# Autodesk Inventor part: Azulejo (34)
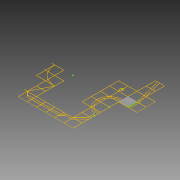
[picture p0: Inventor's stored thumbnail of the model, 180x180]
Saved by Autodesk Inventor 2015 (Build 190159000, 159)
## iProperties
Created: 2015-04
Part Number: Azulejo (34)
Material: Genérico
Document SubType Name: Modeling
Designer: Felipe
Density: 1 g/cm^3
Appearance: Padrão
Author: Felipe
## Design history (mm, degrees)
sketch "Sketch1"
  geometry: L1 (-1510, -7490)-(-1510, -6010); L2 (-3010, -1490)-(-3010, -10); L3 (-2990, 10)-(-1510, 10); L4 (-1510, -10)-(-2990, -10); L5 (-1510, -1490)-(-1510, -10); L6 (-1490, -10)-(-1490, -1490); L7 (-1490, -1490)-(-10, -1490); L8 (-10, -1510)-(-1490, -1510); L9 (-10, -2990)-(-10, -1510); L10 (-10, -5990)-(-10, -4510); L11 (-1490, -7490)-(-10, -7490); L12 (4490, -6010)-(3010, -6010); L13 (10, -1510)-(10, -2990); L14 (10, -3010)-(10, -4490); L15 (10, -4510)-(10, -5990); L16 (10, -5990)-(1490, -5990); L17 (1490, -6010)-(10, -6010); L18 (10, -7490)-(1490, -7490); L19 (1510, -5990)-(2990, -5990); L20 (2990, -6010)-(1510, -6010); L21 (1510, -7490)-(2990, -7490); L22 (4490, 1510)-(4490, 2990); L23 (4490, 10)-(4490, 1490); L24 (4490, -1490)-(4490, -10); L25 (4490, -2990)-(4490, -1510); L26 (3010, -5990)-(4490, -5990); L27 (3010, -7490)-(4490, -7490); L28 (4510, 3010)-(5990, 3010); L29 (5990, 2990)-(4510, 2990); L30 (4510, 2990)-(4510, 1510); L31 (4510, 1510)-(5990, 1510); L32 (5990, 1510)-(5990, 1740.185); L33 (5990, 1760.2)-(5990, 2259.8); L34 (5990, 2279.815)-(5990, 2990); L35 (5990, 1490)-(4510, 1490); L36 (4510, 1490)-(4510, 10); L37 (4510, 10)-(5990, 10); L38 (5990, 10)-(5990, 1490); L39 (5975.983, -10)-(4510, -10); L40 (4510, -10)-(4510, -1490); L41 (5990, -1510)-(5782.897, -1510); L42 (5782.897, -1510)-(5688.66, -1510); L43 (5668.66, -1510)-(5482.895, -1510); L44 (5482.895, -1510)-(5388.656, -1510); L45 (5368.656, -1510)-(4510, -1510); L46 (4510, -1510)-(4510, -2990); L47 (4510, -2990)-(5975.983, -2990); L48 (5990, -2975.728)-(5990, -2837.377); L49 (5990, -2837.377)-(5990, -2536.247); L50 (5990, -2500.476)-(5990, -2317.632); L51 (5990, -2317.632)-(5990, -1510); L52 (5990, -3010)-(4510, -3010); L53 (5990, -4490)-(5990, -3010); L54 (4510, -5990)-(5990, -5990); L55 (5990, -5990)-(5990, -4510); L56 (4510, -7490)-(5990, -7490); L57 (5990, -7490)-(5990, -6310); L58 (5990, -6290)-(5990, -6010); L59 (7490, 4510)-(7490, 5990); L60 (6010, 3010)-(7490, 3010); L61 (7490, 3010)-(7490, 4490); L62 (7490, 2990)-(6010, 2990); L63 (6010, 2990)-(6010, 2279.815); L64 (6010, 2259.8)-(6010, 1760.2)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; A1 r 250 centre (6000, 2010) between (5990, 2259.8) and (5990, 1760.2); A2 r 250 centre (6000, 2010) between (6010, 1760.2) and (6010, 2259.8); A3 r 270 centre (6000, 2010) between (5990, 2279.815) and (5990, 1740.185); A4 r 270 centre (6000, 2010) between (6010, 1740.185) and (6010, 2279.815); A5 r 3010.017 centre (0, 0) between (-1490, -2615.358) and (-346.554, -2990); A6 r 2990.017 centre (0, 0) between (-1490, -2592.316) and (-10, -2990); A7 r 3010.017 centre (0, 0) between (-2603.863, -1510) and (-1510, -2603.863); A8 r 2990.017 centre (0, 0) between (-2580.717, -1510) and (-1510, -2580.717); A9 r 3010.017 centre (0, 0) between (-2990, -346.554) and (-2615.358, -1490); A10 r 2990.017 centre (0, 0) between (-2990, -10) and (-2592.316, -1490); A11 r 2131.367 centre (7500, -1500) between (7490, 631.344) and (6010, 24.017); A12 r 2131.367 centre (7500, -1500) between (5975.983, -10) and (5368.656, -1490); A13 r 2131.367 centre (7500, -1500) between (5368.656, -1510) and (5975.983, -2990); A14 r 2131.367 centre (7500, -1500) between (6010, -3024.017) and (7190, -3608.703); A15 r 1831.367 centre (7500, -1500) between (7490.321, 331.342) and (6463.753, 10); A16 r 1831.367 centre (7500, -1500) between (6435.196, -10) and (6010, -435.196); A17 r 1831.367 centre (7500, -1500) between (5990, -463.753) and (5668.66, -1490); A18 r 1831.367 centre (7500, -1500) between (5668.66, -1510) and (5990, -2536.247); A19 r 1831.367 centre (7500, -1500) between (6010, -2564.804) and (6435.196, -2990); A20 r 1831.367 centre (7500, -1500) between (6463.753, -3010) and (7490, -3331.34); A21 r 2111.367 centre (7500, -1500) between (7490.047, 611.344) and (6024.272, 10); A22 r 2111.367 centre (7500, -1500) between (5990, -24.272) and (5388.656, -1490); A23 r 2111.367 centre (7500, -1500) between (5388.656, -1510) and (5990, -2975.728); A24 r 2111.367 centre (7500, -1500) between (6024.272, -3010) and (7210, -3591.357); A25 r 1811.367 centre (7500, -1500) between (7490.374, 311.342) and (6499.524, 10); A26 r 1811.367 centre (7500, -1500) between (6469.975, -10) and (6010, -469.975); A27 r 1811.367 centre (7500, -1500) between (5990, -499.524) and (5688.66, -1490); A28 r 1811.367 centre (7500, -1500) between (5688.66, -1510) and (5990, -2500.476); A29 r 1811.367 centre (7500, -1500) between (6010, -2530.025) and (6469.975, -2990); A30 r 1811.367 centre (7500, -1500) between (6499.524, -3010) and (7490, -3311.34); A31 r 449.871 centre (7499.449, -4060.672) between (7510, -4510.419) and (7521.546, -4510); 9 further points
  constraints: 722 end point, 64 point on circle, 31 centre point, 11 point on line, 6 parallel, 3 horizontal, 3 perpendicular, 1 other
extrude "Extrusion1" new body sketch "Sketch1" distance "d0" = 60; taper "d1" = 0 deg
extrude "Extrusion2" new body sketch "Sketch1" distance "d2" = 60; taper "d3" = 0 deg
extrude "Extrusion3" new body sketch "Sketch1" distance "d4" = 60; taper "d5" = 0 deg
body "Solid1"
body "Solid2"
body "Solid3"
